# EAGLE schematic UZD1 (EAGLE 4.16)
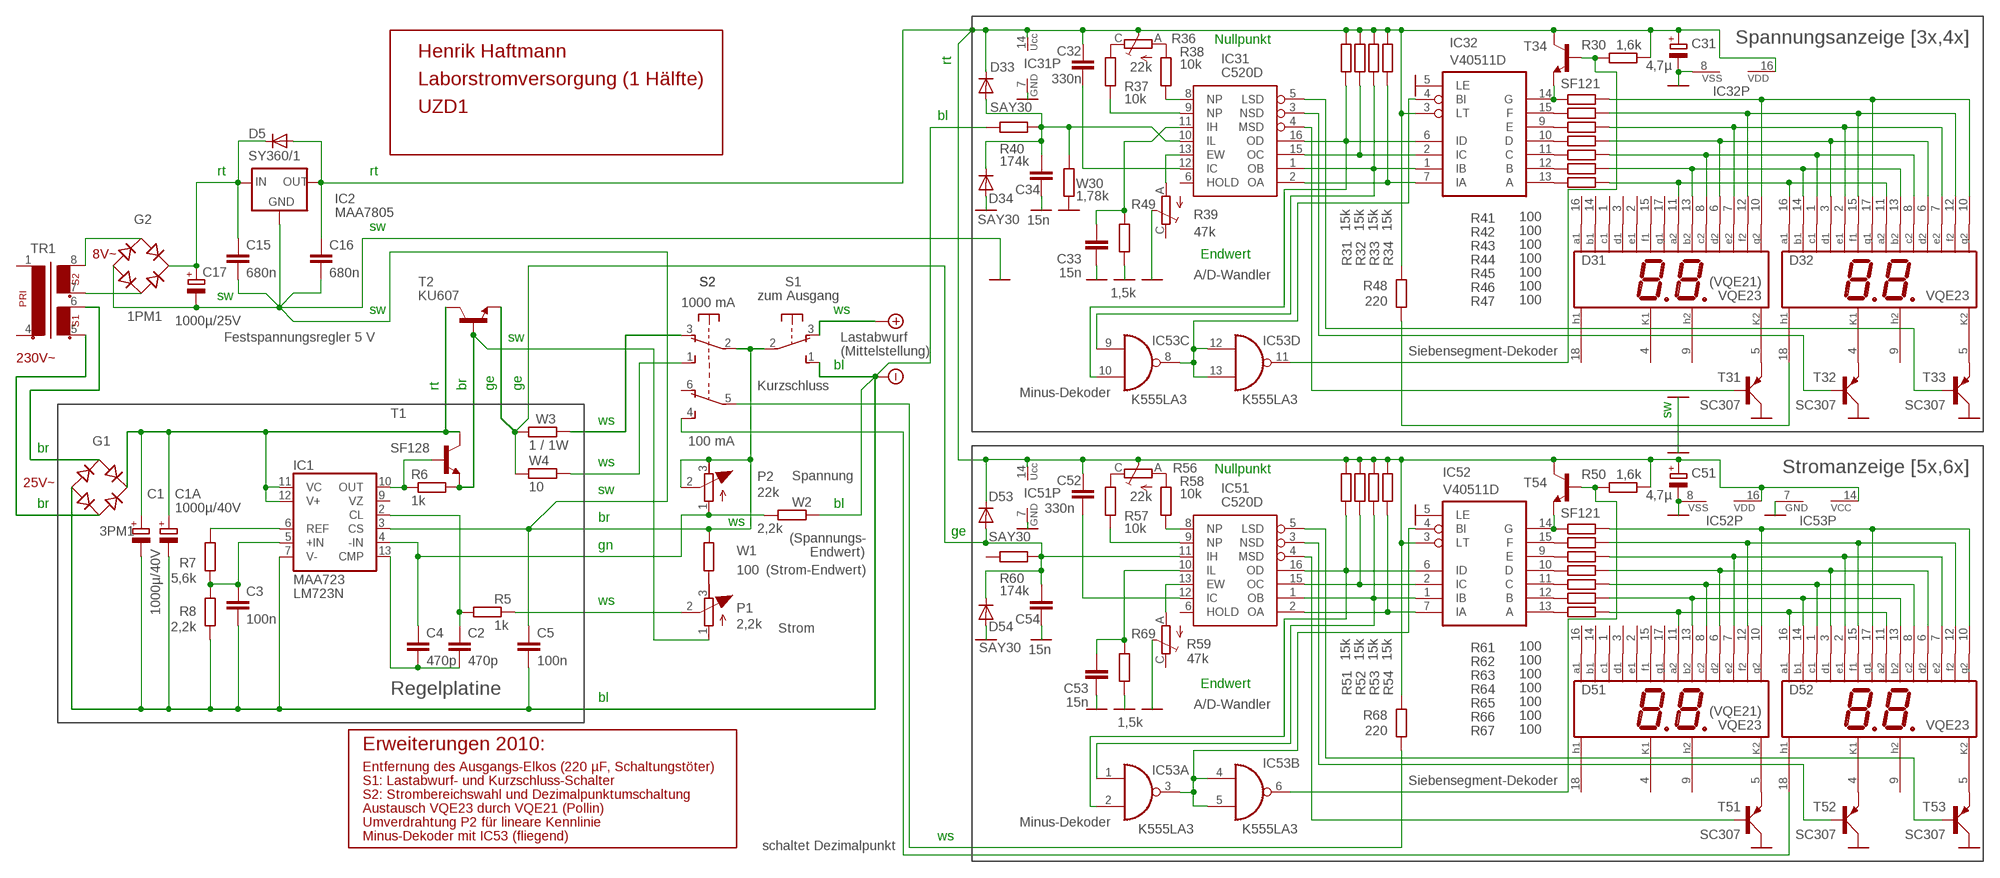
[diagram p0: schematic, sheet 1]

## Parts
C1  1000µ/40V  CPOL-EUE25-10AXIAL  [E25-10]
C1A  1000µ/40V  CPOL-EUE25-10AXIAL  [E25-10]
C2  470p  C-EU025-025X050  [C025-025X050]
C3  100n  C-EU025-025X050  [C025-025X050]
C4  470p  C-EU025-025X050  [C025-025X050]
C5  100n  C-EU025-025X050  [C025-025X050]
C15  680n  C-EU025-025X050  [C025-025X050]
C16  680n  C-EU025-025X050  [C025-025X050]
C17  1000µ/25V  CPOL-EUE25-10AXIAL  [E25-10]
C31  4,7µ  CPOL-EUE2-4  [E2-4]
C32  330n  C1  [C050-050X075]
C33  15n  C  [0603]
C34  15n  C  [0603]
C51  4,7µ  CPOL-EUE2-4  [E2-4]
C52  330n  C1  [C050-050X075]
C53  15n  C  [0603]
C54  15n  C  [0603]
D5  SY360/1  DIODE-C1702-15  [C1702-15]
D31  VQE23  [VQE]
D32  VQE23  [VQE]
D33  SAY30  DD  [SAY]
D34  SAY30  DD  [SAY]
D51  VQE23  [VQE]
D52  VQE23  [VQE]
D53  SAY30  DD  [SAY]
D54  SAY30  DD  [SAY]
G1  3PM1  RECTIFIER-2KBB  [2KBB]
G2  1PM1  RECTIFIER-1KAB  [1KAB]
IC1  MAA723  LM723N  [DIL14]
IC2  MAA7805  78XX-TO3  [TO3-78]
IC31  C520D  [DIL16M]
IC32  V40511D  4511N  [DIL16]
IC51  C520D  [DIL16M]
IC52  V40511D  4511N  [DIL16]
IC53  K555LA3  74LS00N  [DIL14]
P1  2,2k  R-TRIMM64X  [RTRIM64X]
P2  22k  R-TRIMM64X  [RTRIM64X]
R5  1k  R-EU_0207/10  [0207/10]
R6  1k  R-EU_0207/10  [0207/10]
R7  5,6k  R-EU_0207/10  [0207/10]
R8  2,2k  R-EU_0207/10  [0207/10]
R30  1,6k  R  [0207/2V]
R31  15k  R  [0207/2V]
R32  15k  R  [0207/2V]
R33  15k  R  [0207/2V]
R34  15k  R  [0207/2V]
R36  22k  RTRIM  [RTRIM-RFT]
R37  10k  R  [0207/2V]
R38  10k  R  [0207/2V]
R39  47k  RTRIM  [RTRIM-RFT]
R40  174k  R  [0207/2V]
R41  100  R  [0207/2V]
R42  100  R  [0207/2V]
R43  100  R  [0207/2V]
R44  100  R  [0207/2V]
R45  100  R  [0207/2V]
R46  100  R  [0207/2V]
R47  100  R  [0207/2V]
R48  220  R  [0207/2V]
R49  1,5k  R  [0207/2V]
R50  1,6k  R  [0207/2V]
R51  15k  R  [0207/2V]
R52  15k  R  [0207/2V]
R53  15k  R  [0207/2V]
R54  15k  R  [0207/2V]
R56  22k  RTRIM  [RTRIM-RFT]
R57  10k  R  [0207/2V]
R58  10k  R  [0207/2V]
R59  47k  RTRIM  [RTRIM-RFT]
R60  174k  R  [0207/2V]
R61  100  R  [0207/2V]
R62  100  R  [0207/2V]
R63  100  R  [0207/2V]
R64  100  R  [0207/2V]
R65  100  R  [0207/2V]
R66  100  R  [0207/2V]
R67  100  R  [0207/2V]
R68  220  R  [0207/2V]
R69  1,5k  R  [0207/2V]
S1  9077-1  [9077-1]
S2  9077-2  [9077-2]
T1  SF128  -NPN-TO18-  [TO18-]
T2  KU607  -NPN-TO3/  [TO3]
T31  SC307  PNP  [SOT54A]
T32  SC307  PNP  [SOT54A]
T33  SC307  PNP  [SOT54A]
T34  SF121  -NPN-TO18-  [TO18-]
T51  SC307  PNP  [SOT54A]
T52  SC307  PNP  [SOT54A]
T53  SC307  PNP  [SOT54A]
T54  SF121  -NPN-TO18-  [TO18-]
TR1  EE20-2  [EE20-2]
W1  100  R-EU_0207/10  [0207/10]
W2  2,2k  R-EU_0207/10  [0207/10]
W3  1 / 1W  R-EU_0207/10  [0207/10]
W4  10  R-EU_0207/10  [0207/10]
W30  1,78k  R  [0207/2V]

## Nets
5P: C16.1 C31.+ C32.2 C51.+ C52.2 D5.A D33.K D53.K IC2.1(OUT) IC31.14(5P) IC32.3(LT) IC32.16(VDD) IC51.14(5P) IC52.3(LT) IC52.16(VDD) IC53.14(P:VCC) R30.1 R31.1 R32.1 R33.1 R34.1 R36.B(S) R48.1 R50.2 R51.1 R52.1 R53.1 R54.1 R56.B(S) R68.1 T34.3(C) T54.3(C)
+24V: S1.3(O) ; supply symbol labelled 
-24V: C1.- C1A.- C3.2 C5.2 G1.- IC1.7(V-) R8.1 R40.1 S1.1(S) W2.2 ; supply symbol labelled 
A: D31.11(A2) D32.11(A2) D32.16(A1) R47.2
A1: D51.11(A2) D52.11(A2) D52.16(A1) R67.2
B: D31.13(B2) D32.13(B2) D32.14(B1) R46.2
B1: D51.13(B2) D52.13(B2) D52.14(B1) R66.2
C: D31.8(C2) D32.1(C1) D32.8(C2) R45.2
C1: D51.8(C2) D52.1(C1) D52.8(C2) R65.2
D: D31.6(D2) D32.3(D1) D32.6(D2) R44.2
D0: IC31.2(OA) IC32.7(IA) R34.2
D1: IC31.1(OB) IC32.1(IB) IC53.9(C:I0) R33.2
D2: IC31.15(OC) IC32.2(IC) R32.2
D3: IC31.16(OD) IC32.6(ID) IC53.10(C:I1) R31.2
D4: IC51.2(OA) IC52.7(IA) R54.2
D5: IC51.1(OB) IC52.1(IB) IC53.1(A:I0) R53.2
D6: IC51.15(OC) IC52.2(IC) R52.2
D7: IC51.16(OD) IC52.6(ID) IC53.2(A:I1) R51.2
D8: D51.6(D2) D52.3(D1) D52.6(D2) R64.2
E: D31.7(E2) D32.2(E1) D32.7(E2) R43.2
E1: D51.7(E2) D52.2(E1) D52.7(E2) R63.2
EW: IC31.13(EW) R39.A
EW1: IC51.13(EW) R59.A
F: D31.12(F2) D32.12(F2) D32.15(F1) R42.2
F1: D51.12(F2) D52.12(F2) D52.15(F1) R62.2
G: D31.10(G2) D32.10(G2) D32.17(G1) R41.2
G1: D51.10(G2) D52.10(G2) D52.17(G1) R61.2
GND: C5.1 C15.2 C16.2 C17.- C31.- C33.2 C34.2 C51.- C53.2 C54.2 D34.A D54.A G2.- IC1.3(CS) IC2.3(GND) IC31.7(GND) IC32.5(LE) IC32.8(VSS) IC51.7(GND) IC52.5(LE) IC52.8(VSS) IC53.7(P:GND) P2.2(S) P2.3(A) R39.B(S) R49.2 R59.B(S) R69.2 S1.2(P) S2.2(1:P) T31.C T32.C T33.C T51.C T52.C T53.C W1.2 W30.2
IC: C32.1 IC31.12(IC)
IC1: C52.1 IC51.12(IC)
IH1: C54.1 D53.A D54.K IC51.11(IH) R60.2 T2.E W3.1 W4.1
N$1: IC32.14(G) R41.1 T34.1(E)
N$2: IC32.15(F) R42.1
N$3: IC32.9(E) R43.1
N$4: IC32.10(D) R44.1
N$5: IC32.11(C) R45.1
N$6: IC32.12(B) R46.1
N$7: IC32.13(A) R47.1
N$8: D31.5(GK2) T31.E
N$9: D32.4(GK1) T32.E
N$10: D32.5(GK2) T33.E
N$11: IC31.4(MSD) T31.B
N$12: IC31.3(NSD) T32.B
N$13: IC31.5(LSD) T33.B
N$14: D32.18(H1) R48.2
N$15: C4.1 IC1.4(-IN) P2.1(E) W2.1
N$16: C34.1 D33.A D34.K IC31.10(IL) R40.2 W30.1
N$17: R56.A R58.1
N$18: R56.C(E) R57.1
N$19: IC52.14(G) R61.1 T54.1(E)
N$20: IC52.15(F) R62.1
N$21: IC52.9(E) R63.1
N$22: IC52.10(D) R64.1
N$23: C33.1 IC31.11(IH) R49.1
N$24: IC52.11(C) R65.1
N$25: IC52.12(B) R66.1
N$26: IC52.13(A) R67.1
N$27: D51.5(GK2) T51.E
N$28: C2.1 IC1.2(CL) R5.1
N$29: D52.5(GK2) T53.E
N$30: IC52.4(BI) IC53.3(A:O) IC53.4(B:I0) IC53.5(B:I1)
N$31: C53.1 IC51.10(IL) R69.1
N$33: IC53.11(D:O) R30.2 T34.2(B)
N$34: IC51.4(MSD) T51.B
N$35: IC51.3(NSD) T52.B
N$36: IC51.5(LSD) T53.B
N$37: R36.A R38.1
N$38: R36.C(E) R37.1
N$39: D52.4(GK1) T52.E
N$40: IC53.6(B:O) R50.1 T54.2(B)
N$41: G1.AC1 TR1.6
N$42: IC32.4(BI) IC53.8(C:O) IC53.12(D:I0) IC53.13(D:I1)
N$48: D52.18(H1) S2.4(2:S)
N$50: R68.2 S2.5(2:P)
N$51: IC1.6(REF) R7.2
N$52: C3.1 IC1.5(+IN) R7.1 R8.2
N$53: C1.+ C1A.+ G1.+ IC1.11(VC) IC1.12(V+) T1.3(C) T2.C
N$54: IC1.10(OUT) R6.1 T1.2(B)
N$56: P1.1(E) R6.2 T1.1(E) T2.B
N$57: G1.AC2 TR1.5
N$58: S2.3(1:O) W3.2
N$59: S2.1(1:S) W4.2
N$60: C2.2 C4.2 IC1.13(CMP)
N$61: P1.2(S) R5.2
N$62: P1.3(A) W1.1
N$63: G2.AC1 TR1.8
N$64: G2.AC2 TR1.7
N$67: C15.1 C17.+ D5.C G2.+ IC2.2(IN)
NP@1: IC31.8(NP) R38.2
NP@2: IC31.9(NP) R37.2
NP@3: IC51.8(NP) R58.2
NP@4: IC51.9(NP) R57.2
Unconnected: D31.1(C1) D31.2(E1) D31.3(D1) D31.4(GK1) D31.9(H2) D31.14(B1) D31.15(F1) D31.16(A1) D31.17(G1) D31.18(H1) D32.9(H2) D51.1(C1) D51.2(E1) D51.3(D1) D51.4(GK1) D51.9(H2) D51.14(B1) D51.15(F1) D51.16(A1) D51.17(G1) D51.18(H1) D52.9(H2) IC1.9(VZ) IC31.6(HOLD) IC51.6(HOLD) R39.C(E) R59.C(E) R60.1 S2.6(2:O) TR1.1 TR1.4

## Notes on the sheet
- Spannungsanzeige [3x,4x]
- Nullpunkt
- Henrik Haftmann
- rt
- Laborstromversorgung (1 Hälfte)
- UZD1
- bl
- rt | rt
- sw
- 8V~ | Endwert
- A/D-Wandler
- (VQE21)
- sw | zum Ausgang
- 1000 mA
- sw | ws
- Festspannungsregler 5 V | sw | Lastabwurf
- (Mittelstellung) | Siebensegment-Dekoder
- 230V~
- bl
- rt | br | ge | ge | Kurzschluss
- Minus-Dekoder
- sw
- ws
- 100 mA
- br
- Stromanzeige [5x,6x]
- ws
- Nullpunkt
- Spannung
- 25V~
- sw
- br | bl
- br
- ws
- ge
- (Spannungs-
- gn
- Endwert)
- (Strom-Endwert)
- LM723N
- ws
- Strom
- Endwert
- Regelplatine
- bl
- A/D-Wandler
- (VQE21)
- Erweiterungen 2010:
- Entfernung des Ausgangs-Elkos (220 µF, Schaltungstöter)
- S1: Lastabwurf- und Kurzschluss-Schalter | Siebensegment-Dekoder
- S2: Strombereichswahl und Dezimalpunktumschaltung
- Austausch VQE23 durch VQE21 (Pollin)
- Umverdrahtung P2 für lineare Kennlinie | Minus-Dekoder
- Minus-Dekoder mit IC53 (fliegend) | schaltet Dezimalpunkt | ws

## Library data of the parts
C1 C1A C17 C31 C51 = rcl:CPOL-EU: POLARIZED CAPACITOR, European symbol
C2-C5 C15 C16 = rcl:C-EU: CAPACITOR, European symbol
C32-C34 C52-C54 = us1:C: Kondensator
D5 = diode:DIODE-: DIODE
D31 D32 D51 D52 = uzd1:VQE*: LED-Anzeige 2 7-Segment-Ziffern 8.8.
D33 D34 D53 D54 = sm:D: Diode
G1 G2 = rectifier:RECTIFIER-: Rectifier
IC1 = linear:*723: Positive VOLTAGE REGULATOR
IC2 = v-reg:78XX-TO3: VOLTAGE REGULATOR
IC31 IC51 = us1:C520: A/D-Wandler 3-stellig -99mV..999mV HOLD-EingangBetriebsart 0..0.4 VUmsetzung 4 Sa/s 0,8..1,6 VMesswert halten 3,2..5,5 VUmsetzung 100 Sa/s Standard-Beschaltung: NP: 13 k&Omega; fest + 10 k&Omega; Poti nach + 13 k&Omega; fest IC: 330 nF nach Masse (hochwertiger Kondensator!) EW: 22 k&Omega; Poti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
IC32 IC52 = 45xx:4511: BCD to 7-segment LATCH/DECODER/DRIVER
IC53 = 74xx-eu:74*00: Quad 2-input NAND gate
P1 P2 = rcl:R-TRIMM: Trimm resistor
R5-R8 W1-W4 = rcl:R-EU_: RESISTOR, European symbol
R30-R34 R37 R38 R40-R54 R57 R58 R60-R69 W30 = us1:R: Widerstand
R36 R39 R56 R59 = us1:RTRIM: Einstell-Potenziometer
S1 = switch-misc:9077-1: MARQUARDT SWITCH
S2 = switch-misc:9077-2: MARQUARDT SWITCH
T1 T2 T34 T54 = transistor:*-NPN-: NPN Transistror
T31-T33 T51-T53 = us1:PNP: pnp-Transistor
TR1 = trafo:EE20-2: TRANSFORMER 1 primary winding, 2 secondary windings ERA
